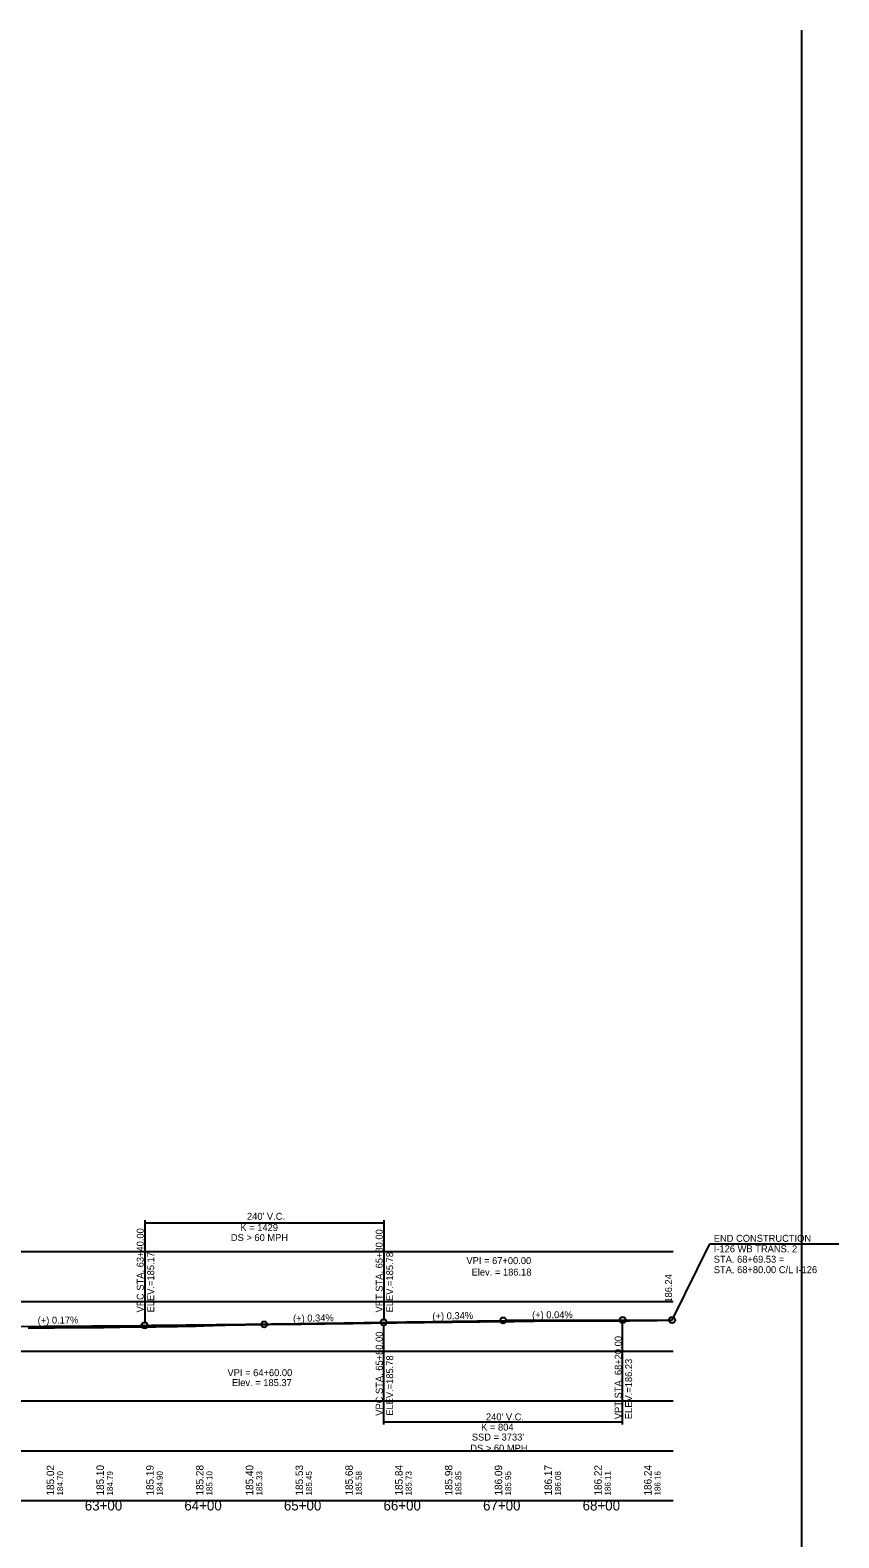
# Model space of a CAD drawing. Extents: x 69 to 2003113, y 512 to 837401.
# Drawn here: x 1893602 to 1894415, y 821763 to 823277 of the extents above; entities that cross this region are included whole.
import ezdxf

# ---------------------------------------------------------------- set-up
doc = ezdxf.new("R2010")
doc.units = 0
for name, color, linetype in [('BR_AUTO DIMENSION', 7, 'Continuous'), ('BR_BORDER LINES', 7, 'Continuous'), ('BR_CENTER LINE BASELINE', 7, 'Continuous'), ('BR_CONCRETE', 7, 'Continuous'), ('BR_GRID DOTS', 7, 'Continuous'), ('BR_GRID LINES', 7, 'Continuous'), ('BR_TEXT', 7, 'Continuous'), ('RD_HC_Points', 7, 'Continuous'), ('RD_SHT_ID', 7, 'Continuous'), ('RD_SHT_IplotShp', 7, 'Continuous')]:
    doc.layers.add(name, color=color, linetype=linetype)

msp = doc.modelspace()

# ---------------------------------------------------------------- linework, layer by layer
at = {"layer": 'BR_AUTO DIMENSION'}
for p, q in [((1894377.5, 820550.1), (1894377.5, 823276.6)), ((1891422.5, 822050.1), (1894248.3, 822050.1)), ((1891422.5, 822000.1), (1894248.3, 822000.1)), ((1891422.5, 821950.1), (1894248.3, 821950.1)), ((1891422.5, 821900.1), (1894248.3, 821900.1)), ((1891422.5, 821850.1), (1894248.3, 821850.1)), ((1891422.5, 821800.1), (1894248.3, 821800.1))]:
    msp.add_line(p, q, dxfattribs=at)
at = {"layer": 'BR_BORDER LINES'}
msp.add_line((1891422.5, 821800.1), (1893922.5, 821800.1), dxfattribs=at)
at = {"layer": 'BR_CENTER LINE BASELINE'}
for p, q in [((1894006.5, 821979.8), (1894074.5, 821981)), ((1894148.5, 821981.2), (1894080.5, 821981)), ((1893766.5, 821976.4), (1893834.5, 821977)), ((1893908.5, 821978.2), (1893840.5, 821977))]:
    msp.add_line(p, q, dxfattribs=at)
for centre in [(1893837.5, 821977), (1894077.5, 821981), (1894247.1, 821981.3), (1894247.1, 821981.3), (1894247.1, 821981.3)]:
    msp.add_circle(centre, 3, dxfattribs=at)
at = {"layer": 'BR_GRID DOTS'}
for p, q in [((1893717.5, 822081.5), (1893717.5, 821979)), ((1893717.5, 822079), (1893957.5, 822079)), ((1893957.5, 822081.5), (1893957.5, 821982)), ((1893957.5, 821876.5), (1893957.5, 821976)), ((1894197.5, 821876.5), (1894197.5, 821978.3)), ((1893957.5, 821879), (1894197.5, 821879))]:
    msp.add_line(p, q, dxfattribs=at)
for points in [[(1894247.1, 821981.3), (1894284.9, 822057.8)], [(1894284.9, 822057.8), (1894414.6, 822057.8)]]:
    msp.add_lwpolyline(points, dxfattribs=at)
for centre in [(1893717.5, 821976), (1893957.5, 821979), (1893957.5, 821979), (1894197.5, 821981.3)]:
    msp.add_circle(centre, 3, dxfattribs=at)
at = {"layer": 'BR_GRID LINES'}
for p, q in [((1894197.5, 821981.3), (1894247.1, 821981.3)), ((1893427.5, 821973.5), (1893712.5, 821975.9)), ((1893712.5, 821975.9), (1893717.5, 821976))]:
    msp.add_line(p, q, dxfattribs=at)
for points in [[(1893717.5, 821976), (1893722.3, 821976), (1893727.1, 821976.1), (1893731.9, 821976.1), (1893736.7, 821976.1), (1893741.5, 821976.2), (1893746.3, 821976.2), (1893751.1, 821976.3), (1893755.9, 821976.3), (1893760.7, 821976.4), (1893765.5, 821976.4), (1893770.3, 821976.5), (1893775.1, 821976.5), (1893779.9, 821976.6), (1893784.7, 821976.6), (1893789.5, 821976.7), (1893794.3, 821976.7), (1893799.1, 821976.8), (1893803.9, 821976.8), (1893808.7, 821976.9), (1893813.5, 821976.9), (1893818.3, 821977), (1893823.1, 821977.1), (1893827.9, 821977.1), (1893832.7, 821977.2), (1893837.5, 821977.2), (1893842.3, 821977.3), (1893847.1, 821977.4), (1893851.9, 821977.4), (1893856.7, 821977.5), (1893861.5, 821977.5), (1893866.3, 821977.6), (1893871.1, 821977.7), (1893875.9, 821977.7), (1893880.7, 821977.8), (1893885.5, 821977.9), (1893890.3, 821978), (1893895.1, 821978), (1893899.9, 821978.1), (1893904.7, 821978.2), (1893909.5, 821978.2), (1893914.3, 821978.3), (1893919.1, 821978.4), (1893923.9, 821978.5), (1893928.7, 821978.5), (1893933.5, 821978.6), (1893938.3, 821978.7), (1893943.1, 821978.8), (1893947.9, 821978.8), (1893952.7, 821978.9), (1893957.5, 821979)], [(1893957.5, 821979), (1893962.3, 821979.1), (1893967.1, 821979.2), (1893971.9, 821979.2), (1893976.7, 821979.3), (1893981.5, 821979.4), (1893986.3, 821979.5), (1893991.1, 821979.5), (1893995.9, 821979.6), (1894000.7, 821979.7), (1894005.5, 821979.7), (1894010.3, 821979.8), (1894015.1, 821979.9), (1894019.9, 821979.9), (1894024.7, 821980), (1894029.5, 821980.1), (1894034.3, 821980.1), (1894039.1, 821980.2), (1894043.9, 821980.2), (1894048.7, 821980.3), (1894053.5, 821980.3), (1894058.3, 821980.4), (1894063.1, 821980.4), (1894067.9, 821980.5), (1894072.7, 821980.5), (1894077.5, 821980.6), (1894082.3, 821980.6), (1894087.1, 821980.7), (1894091.9, 821980.7), (1894096.7, 821980.7), (1894101.5, 821980.8), (1894106.3, 821980.8), (1894111.1, 821980.9), (1894115.9, 821980.9), (1894120.7, 821980.9), (1894125.5, 821981), (1894130.3, 821981), (1894135.1, 821981), (1894139.9, 821981), (1894144.7, 821981.1), (1894149.5, 821981.1), (1894154.3, 821981.1), (1894159.1, 821981.1), (1894163.9, 821981.2), (1894168.7, 821981.2), (1894173.5, 821981.2), (1894178.3, 821981.2), (1894183.1, 821981.2), (1894187.9, 821981.2), (1894192.7, 821981.2), (1894197.5, 821981.3)]]:
    msp.add_spline(points, degree=3, dxfattribs=at)
at = {"layer": 'BR_TEXT'}
for points in [[(1893822.5, 821976.7), (1893824.5, 821976.7), (1893826.5, 821976.7), (1893828.5, 821976.8), (1893830.5, 821976.8), (1893832.5, 821976.9), (1893834.5, 821976.9), (1893836.5, 821976.9), (1893838.5, 821977), (1893840.5, 821977), (1893842.5, 821977), (1893844.5, 821977.1), (1893846.5, 821977.1), (1893848.5, 821977.1), (1893850.5, 821977.1), (1893852.5, 821977.1), (1893854.5, 821977.1), (1893856.5, 821977.1), (1893858.5, 821977.1), (1893860.5, 821977.2), (1893862.5, 821977.2), (1893864.5, 821977.2), (1893866.5, 821977.2), (1893868.5, 821977.3), (1893870.5, 821977.3), (1893872.5, 821977.3), (1893874.5, 821977.3), (1893876.5, 821977.4), (1893878.5, 821977.4), (1893880.5, 821977.4), (1893882.5, 821977.5), (1893884.5, 821977.5), (1893886.5, 821977.5), (1893888.5, 821977.5), (1893890.5, 821977.5), (1893892.5, 821977.6), (1893894.5, 821977.6), (1893896.5, 821977.6), (1893898.5, 821977.6), (1893900.5, 821977.7), (1893902.5, 821977.7), (1893904.5, 821977.7), (1893906.5, 821977.8), (1893908.5, 821977.8), (1893910.5, 821977.8), (1893912.5, 821977.9), (1893914.5, 821977.9), (1893916.5, 821977.9), (1893918.5, 821977.9), (1893920.5, 821978), (1893922.5, 821978), (1893924.5, 821978), (1893926.5, 821978), (1893928.5, 821978.1), (1893930.5, 821978.1), (1893932.5, 821978.1), (1893934.5, 821978.2), (1893936.5, 821978.2), (1893938.5, 821978.2), (1893940.5, 821978.3), (1893942.5, 821978.3), (1893944.5, 821978.3), (1893946.5, 821978.4), (1893948.5, 821978.4), (1893950.5, 821978.4), (1893952.5, 821978.4), (1893954.5, 821978.4), (1893956.5, 821978.5), (1893958.5, 821978.5), (1893960.5, 821978.5), (1893962.5, 821978.5), (1893964.5, 821978.6), (1893966.5, 821978.6), (1893968.5, 821978.6), (1893970.5, 821978.6), (1893972.5, 821978.7), (1893974.5, 821978.7), (1893976.5, 821978.8), (1893978.5, 821978.8), (1893980.5, 821978.8), (1893982.5, 821978.8), (1893984.5, 821978.9), (1893986.5, 821978.9), (1893988.5, 821978.9), (1893990.5, 821979), (1893992.5, 821979), (1893994.5, 821979), (1893996.5, 821979), (1893998.5, 821979), (1894000.5, 821979.1), (1894002.5, 821979.1), (1894004.5, 821979.1), (1894006.5, 821979.1), (1894008.5, 821979.1), (1894010.5, 821979.2), (1894012.5, 821979.2), (1894014.5, 821979.2), (1894016.5, 821979.2), (1894018.5, 821979.3), (1894020.5, 821979.3), (1894022.5, 821979.3)], [(1894022.5, 821979.3), (1894024.5, 821979.3), (1894026.5, 821979.3), (1894028.5, 821979.4), (1894030.5, 821979.4), (1894032.5, 821979.4), (1894034.5, 821979.5), (1894036.5, 821979.5), (1894038.5, 821979.5), (1894040.5, 821979.6), (1894042.5, 821979.6), (1894044.5, 821979.6), (1894046.5, 821979.6), (1894048.5, 821979.7), (1894050.5, 821979.7), (1894052.5, 821979.7), (1894054.5, 821979.7), (1894056.5, 821979.8), (1894058.5, 821979.8), (1894060.5, 821979.8), (1894062.5, 821979.8), (1894064.5, 821979.8), (1894066.5, 821979.8), (1894068.5, 821979.8), (1894070.5, 821979.8), (1894072.5, 821979.9), (1894074.5, 821979.9), (1894076.5, 821979.9), (1894078.5, 821979.9), (1894080.5, 821979.9), (1894082.5, 821980), (1894084.5, 821980), (1894086.5, 821980), (1894088.5, 821980), (1894090.5, 821980.1), (1894092.5, 821980.1), (1894094.5, 821980.2), (1894096.5, 821980.2), (1894098.5, 821980.2), (1894100.5, 821980.2), (1894102.5, 821980.2), (1894104.5, 821980.2), (1894106.5, 821980.3), (1894108.5, 821980.3), (1894110.5, 821980.4), (1894112.5, 821980.4), (1894114.5, 821980.5), (1894116.5, 821980.5), (1894118.5, 821980.5), (1894120.5, 821980.5), (1894122.5, 821980.5), (1894124.5, 821980.5), (1894126.5, 821980.5), (1894128.5, 821980.5), (1894130.5, 821980.6), (1894132.5, 821980.6), (1894134.5, 821980.6), (1894136.5, 821980.6), (1894138.5, 821980.6), (1894140.5, 821980.6), (1894142.5, 821980.6), (1894144.5, 821980.6), (1894146.5, 821980.6), (1894148.5, 821980.6), (1894150.5, 821980.6), (1894152.5, 821980.6), (1894154.5, 821980.6), (1894156.5, 821980.6), (1894158.5, 821980.7), (1894160.5, 821980.7), (1894162.5, 821980.7), (1894164.5, 821980.7), (1894166.5, 821980.7), (1894168.5, 821980.7), (1894170.5, 821980.7), (1894172.5, 821980.7), (1894174.5, 821980.7), (1894176.5, 821980.7), (1894178.5, 821980.6), (1894180.5, 821980.6), (1894182.5, 821980.7), (1894184.5, 821980.7), (1894186.5, 821980.7), (1894188.5, 821980.7), (1894190.5, 821980.7), (1894192.5, 821980.7), (1894194.5, 821980.7), (1894196.5, 821980.7), (1894198.5, 821980.7), (1894200.5, 821980.7), (1894202.5, 821980.7), (1894204.5, 821980.7), (1894206.5, 821980.8), (1894208.5, 821980.8), (1894210.5, 821980.8), (1894212.5, 821980.8), (1894214.5, 821980.8), (1894216.5, 821980.8), (1894218.5, 821980.8), (1894220.5, 821980.9), (1894222.5, 821980.9)], [(1894222.5, 821980.9), (1894224.5, 821980.9), (1894226.5, 821980.9), (1894228.5, 821981), (1894230.5, 821981), (1894232.5, 821981), (1894234.5, 821981.1), (1894236.5, 821981.1), (1894238.5, 821981.2), (1894240.5, 821981.2), (1894242.5, 821981.2), (1894244.5, 821981.3), (1894246.5, 821981.3), (1894247.1, 821981.3)], [(1893600.5, 821973.5), (1893602.5, 821973.5), (1893604.5, 821973.5), (1893606.5, 821973.5), (1893608.5, 821973.5), (1893610.5, 821973.5), (1893612.5, 821973.5), (1893614.5, 821973.5), (1893616.5, 821973.5), (1893618.5, 821973.5), (1893620.5, 821973.5), (1893622.5, 821973.6)], [(1893622.5, 821973.6), (1893624.5, 821973.6), (1893626.5, 821973.6), (1893628.5, 821973.7), (1893630.5, 821973.7), (1893632.5, 821973.7), (1893634.5, 821973.7), (1893636.5, 821973.7), (1893638.5, 821973.7), (1893640.5, 821973.7), (1893642.5, 821973.7), (1893644.5, 821973.7), (1893646.5, 821973.7), (1893648.5, 821973.7), (1893650.5, 821973.7), (1893652.5, 821973.7), (1893654.5, 821973.7), (1893656.5, 821973.7), (1893658.5, 821973.7), (1893660.5, 821973.8), (1893662.5, 821973.8), (1893664.5, 821973.8), (1893666.5, 821973.8), (1893668.5, 821973.8), (1893670.5, 821973.9), (1893672.5, 821973.9), (1893674.5, 821974), (1893676.5, 821974), (1893678.5, 821974.1), (1893680.5, 821974.1), (1893682.5, 821974.2), (1893684.5, 821974.2), (1893686.5, 821974.2), (1893688.5, 821974.3), (1893690.5, 821974.3), (1893692.5, 821974.3), (1893694.5, 821974.4), (1893696.5, 821974.4), (1893698.5, 821974.4), (1893700.5, 821974.4), (1893702.5, 821974.4), (1893704.5, 821974.4), (1893706.5, 821974.5), (1893708.5, 821974.5), (1893710.5, 821974.5), (1893712.5, 821974.6), (1893714.5, 821974.6), (1893716.5, 821974.6), (1893718.5, 821974.6), (1893720.5, 821974.6), (1893722.5, 821974.6), (1893724.5, 821974.6), (1893726.5, 821974.6), (1893728.5, 821974.6), (1893730.5, 821974.7), (1893732.5, 821974.7), (1893734.5, 821974.7), (1893736.5, 821974.7), (1893738.5, 821974.8), (1893740.5, 821974.8), (1893742.5, 821974.8), (1893744.5, 821974.9), (1893746.5, 821974.9), (1893748.5, 821975), (1893750.5, 821975), (1893752.5, 821975.1), (1893754.5, 821975.2), (1893756.5, 821975.2), (1893758.5, 821975.2), (1893760.5, 821975.2), (1893762.5, 821975.3), (1893764.5, 821975.3), (1893766.5, 821975.3), (1893768.5, 821975.3), (1893770.5, 821975.4), (1893772.5, 821975.5), (1893774.5, 821975.5), (1893776.5, 821975.6), (1893778.5, 821975.7), (1893780.5, 821975.8), (1893782.5, 821975.8), (1893784.5, 821975.9), (1893786.5, 821976), (1893788.5, 821976.1), (1893790.5, 821976.1), (1893792.5, 821976.2), (1893794.5, 821976.2), (1893796.5, 821976.3), (1893798.5, 821976.3), (1893800.5, 821976.4), (1893802.5, 821976.4), (1893804.5, 821976.4), (1893806.5, 821976.5), (1893808.5, 821976.5), (1893810.5, 821976.5), (1893812.5, 821976.6), (1893814.5, 821976.6), (1893816.5, 821976.6), (1893818.5, 821976.6), (1893820.5, 821976.7), (1893822.5, 821976.7)]]:
    msp.add_lwpolyline(points, dxfattribs=at)

# ---------------------------------------------------------------- texts
at = {"layer": 'BR_CENTER LINE BASELINE'}
for s, rotation, p in [('(+) 0.17%', 0.4837, (1893610, 821977.6)), ('(+) 0.34%', 0.9648, (1893866.5, 821979.5)), ('(+) 0.34%', 0.9648, (1894006.5, 821981.8)), ('(+) 0.04%', 0.1095, (1894106.5, 821983.1))]:
    msp.add_text(s, height=7, rotation=rotation, dxfattribs=at).set_placement(p)
at = {"layer": 'BR_CONCRETE'}
for s, height, p in [('VPC STA. 63+40.00 ', 7, (1893716.5, 821989)), ('VPT STA. 65+80.00 ', 7, (1893956.5, 821989)), ('ELEV.=185.17', 7, (1893727, 821989)), ('ELEV.=185.78', 7, (1893967, 821989)), ('VPC STA. 65+80.00 ', 7, (1893956.5, 821885.2)), ('VPT STA. 68+20.00 ', 7, (1894196.5, 821881.8)), ('ELEV.=185.78', 7, (1893967, 821885.2)), ('ELEV.=186.23', 7, (1894207, 821881.8)), ('184.70', 6, (1893635.5, 821805.1)), ('184.79', 6, (1893685.5, 821805.1)), ('184.90', 6, (1893735.5, 821805.1)), ('185.10', 6, (1893785.5, 821805.1)), ('185.33', 6, (1893835.5, 821805.1)), ('185.45', 6, (1893885.5, 821805.1)), ('185.58', 6, (1893935.5, 821805.1)), ('185.73', 6, (1893985.5, 821805.1)), ('185.85', 6, (1894035.5, 821805.1)), ('185.95', 6, (1894085.5, 821805.1)), ('186.08', 6, (1894135.5, 821805.1)), ('186.11', 6, (1894185.5, 821805.1)), ('186.16', 6, (1894235.5, 821805.1))]:
    msp.add_text(s, height=height, rotation=90, dxfattribs=at).set_placement(p)
at = {"layer": 'BR_GRID DOTS'}
for s, p in [("240' V.C.", (1893820.2, 822082)), ('K = 1429', (1893813.6, 822070.7)), ('DS > 60 MPH', (1893804, 822060.7)), ('K = 804', (1894055.4, 821870.3)), ("240' V.C.", (1894060.2, 821880.6)), ("SSD = 3733'", (1894046, 821860.3)), ('DS > 60 MPH', (1894044.5, 821849.2))]:
    msp.add_text(s, height=7, dxfattribs=at).set_placement(p)
at = {"layer": 'RD_HC_Points'}
for s, p in [('185.02', (1893626.5, 821805.1)), ('185.10', (1893676.5, 821805.1)), ('185.19', (1893726.5, 821805.1)), ('185.28', (1893776.5, 821805.1)), ('185.40', (1893826.5, 821805.1)), ('185.53', (1893876.5, 821805.1)), ('185.68', (1893926.5, 821805.1)), ('185.84', (1893976.5, 821805.1)), ('185.98', (1894026.5, 821805.1)), ('186.09', (1894076.5, 821805.1)), ('186.17', (1894126.5, 821805.1)), ('186.22', (1894176.5, 821805.1)), ('186.24', (1894226.5, 821805.1))]:
    msp.add_text(s, height=7.5, rotation=90, dxfattribs=at).set_placement(p)
at = {"layer": 'RD_SHT_ID'}
for s, p in [('63+00', (1893657.3, 821790.1)), ('64+00', (1893757.3, 821790.1)), ('65+00', (1893857.3, 821790.1)), ('66+00', (1893957.3, 821790.1)), ('67+00', (1894057.3, 821790.1)), ('68+00', (1894157.3, 821790.1))]:
    msp.add_text(s, height=10, dxfattribs=at).set_placement(p)
at = {"layer": 'RD_SHT_IplotShp'}
for s, p in [('END CONSTRUCTION', (1894289, 822059.9)), ('I-126 WB TRANS. 2', (1894289, 822049.4)), ('VPI = 67+00.00', (1894040.6, 822037.5)), ('STA. 68+69.53 =', (1894289, 822038.9)), ('Elev. = 186.18', (1894045.8, 822026)), ('STA. 68+80.00 C/L I-126', (1894289, 822028.4)), ('VPI = 64+60.00', (1893800.6, 821925)), ('Elev. = 185.37', (1893805.1, 821915))]:
    msp.add_text(s, height=7, dxfattribs=at).set_placement(p)
msp.add_text('186.24', height=7, rotation=90, dxfattribs=at).set_placement((1894247.1, 821998.8))

doc.saveas('drawing.dxf')
